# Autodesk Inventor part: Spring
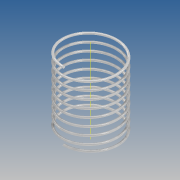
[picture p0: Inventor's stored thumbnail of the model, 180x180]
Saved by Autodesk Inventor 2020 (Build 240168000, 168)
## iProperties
Created: 2019-10
Part Number: Spring
Material: Generic
Document SubType Name: Modeling
Designer: yello
Density: 1 g/cm^3
Appearance: Default
Author: yello
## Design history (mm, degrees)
sketch "Sketch1"
  geometry: L1 (0, 0)-(8, 0); L2 (0, 0)-(0, 3.1); C1 r 0.125 at (0, 3.1)
  constraints: 4 end point, 1 centre point, 1 coincident, 1 horizontal, 1 vertical
  dimensions: "d0" = 8 distance of L1.start L1.end; "d1" = 3.1 distance of L1.start L2.end; "d2" = 0.25 diameter of C1
coil "Coil1" sketch "Sketch1" pitch "d3" = 0.9; turns "d5" = 8.5; dims "d4" = 10, "d6" = 0, angle "d7" = 90 deg, angle "d8" = 90 deg, "d9" = 0, "d10" = 0
body "Solid1"
